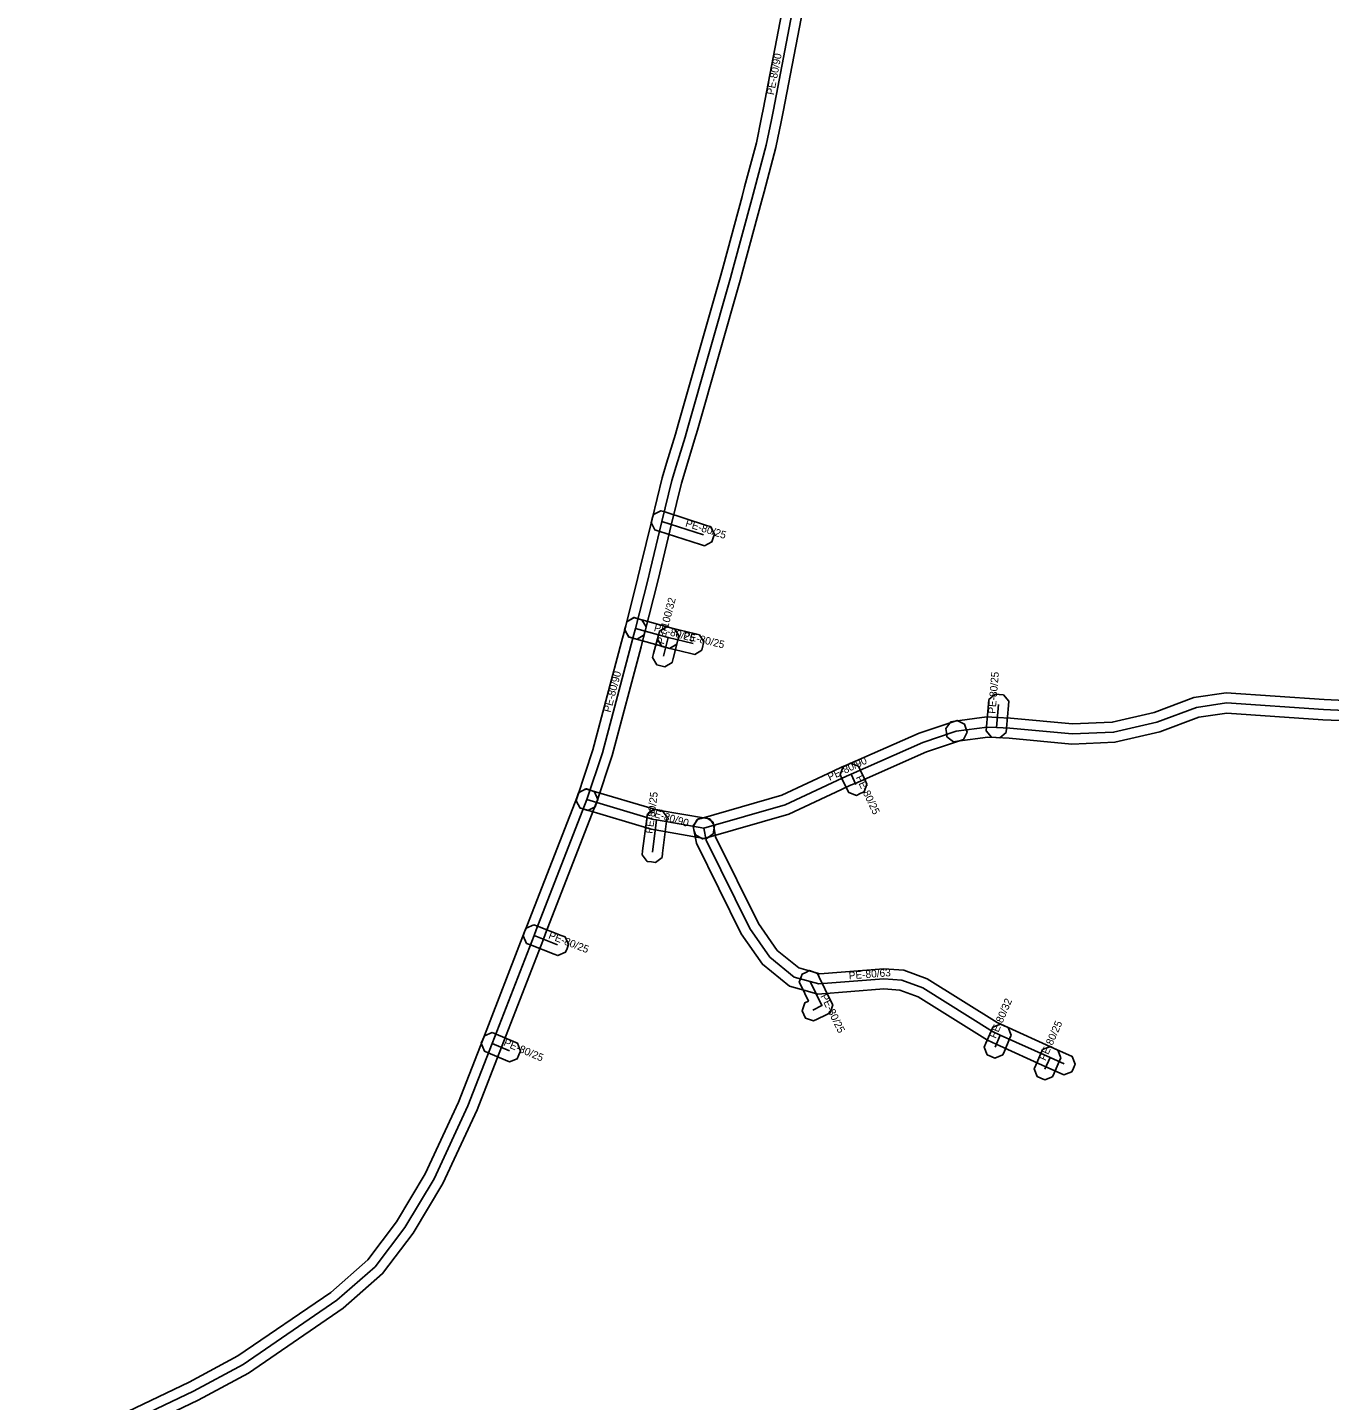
# Model space of a CAD drawing. Extents: x -569373 to -565022, y -1135090 to -1131496.
# Drawn here: x -565661.8 to -565532.3, y -1134134.8 to -1133998.2 of the extents above; entities that cross this region are included whole.
import ezdxf

# ---------------------------------------------------------------- set-up
doc = ezdxf.new("R2010")
doc.units = 0
for name, color, linetype in [('1', 7, 'Continuous'), ('24', 7, 'Continuous'), ('30', 7, 'Continuous')]:
    doc.layers.add(name, color=color, linetype=linetype)

msp = doc.modelspace()

# ---------------------------------------------------------------- linework, layer by layer
at = {"layer": '1'}
for points in [[(-565584.467, -1133995.37), (-565586.619, -1134006.586), (-565586.825, -1134007.573), (-565587.357, -1134010.131), (-565588.534, -1134014.548), (-565588.794, -1134015.52), (-565590.644, -1134022.38), (-565590.906, -1134023.357), (-565595.164, -1134038.244), (-565595.441, -1134039.212), (-565596.318, -1134042.112), (-565596.745, -1134043.523), (-565597.728, -1134047.576), (-565598.903, -1134052.424), (-565599.139, -1134053.401), (-565600.361, -1134058.216), (-565600.463, -1134058.617), (-565601.175, -1134059.041), (-565601.576, -1134058.939), (-565601.977, -1134058.837), (-565602.401, -1134058.125), (-565602.299, -1134057.724), (-565601.081, -1134052.919), (-565600.847, -1134051.954), (-565599.672, -1134047.104), (-565598.675, -1134042.997), (-565598.232, -1134041.532), (-565597.359, -1134038.648), (-565597.086, -1134037.694), (-565592.834, -1134022.823), (-565592.576, -1134021.86), (-565590.726, -1134015), (-565590.466, -1134014.032), (-565589.303, -1134009.669), (-565588.783, -1134007.165), (-565588.581, -1134006.194), (-565586.453, -1133995.11)], [(-565527.938, -1134067.272), (-565532.937, -1134067.048), (-565542.49, -1134066.385), (-565545.28, -1134066.804), (-565549.161, -1134068.239), (-565553.623, -1134069.285), (-565557.906, -1134069.472), (-565564.16, -1134068.878), (-565565.454, -1134068.819), (-565566.284, -1134068.783), (-565569.275, -1134069.191), (-565569.685, -1134069.247), (-565570.345, -1134068.745), (-565570.401, -1134068.335), (-565570.457, -1134067.925), (-565569.955, -1134067.265), (-565569.545, -1134067.209), (-565566.376, -1134066.777), (-565565.366, -1134066.821), (-565564.02, -1134066.882), (-565557.854, -1134067.468), (-565553.897, -1134067.295), (-565549.739, -1134066.321), (-565545.78, -1134064.856), (-565542.57, -1134064.375), (-565532.823, -1134065.052), (-565527.962, -1134065.268)], [(-565661.815, -1134140.62), (-565645.743, -1134132.948), (-565640.881, -1134130.325), (-565631.644, -1134124.008), (-565627.957, -1134120.776), (-565625.11, -1134117), (-565622.244, -1134112.23), (-565618.92, -1134105.078), (-565616.512, -1134098.888), (-565612.352, -1134088.156), (-565612.131, -1134087.596), (-565607.092, -1134074.638), (-565606.942, -1134074.252), (-565606.184, -1134073.918), (-565605.798, -1134074.068), (-565605.412, -1134074.218), (-565605.078, -1134074.976), (-565605.228, -1134075.362), (-565610.269, -1134088.324), (-565610.488, -1134088.884), (-565614.648, -1134099.612), (-565617.08, -1134105.862), (-565620.476, -1134113.17), (-565623.45, -1134118.12), (-565626.483, -1134122.144), (-565630.416, -1134125.592), (-565639.839, -1134132.035), (-565644.837, -1134134.732), (-565660.985, -1134142.44)]]:
    msp.add_lwpolyline(points, dxfattribs=at)
for points in [[(-565594.461, -1134049.748), (-565594.855, -1134049.622), (-565599.005, -1134048.292), (-565599.399, -1134048.166), (-565599.778, -1134047.429), (-565599.652, -1134047.035), (-565599.526, -1134046.641), (-565598.789, -1134046.262), (-565598.395, -1134046.388), (-565594.245, -1134047.718), (-565593.851, -1134047.844), (-565593.472, -1134048.581), (-565593.598, -1134048.975), (-565593.724, -1134049.369)], [(-565600.258, -1134057.819), (-565600.362, -1134058.22), (-565600.522, -1134058.84), (-565600.773, -1134059.814), (-565603.651, -1134070.617), (-565605.211, -1134075.315), (-565605.341, -1134075.708), (-565606.082, -1134076.079), (-565606.475, -1134075.949), (-565606.868, -1134075.819), (-565607.239, -1134075.078), (-565607.109, -1134074.685), (-565605.569, -1134070.043), (-565602.707, -1134059.306), (-565602.458, -1134058.34), (-565602.298, -1134057.72), (-565602.194, -1134057.319), (-565601.481, -1134056.898), (-565601.08, -1134057.002), (-565600.679, -1134057.106)], [(-565597.94, -1134059.954), (-565598.339, -1134059.843), (-565601.599, -1134058.933), (-565601.998, -1134058.822), (-565602.404, -1134058.1), (-565602.293, -1134057.701), (-565602.182, -1134057.302), (-565601.46, -1134056.896), (-565601.061, -1134057.007), (-565597.801, -1134057.917), (-565597.402, -1134058.028), (-565596.996, -1134058.75), (-565597.107, -1134059.149), (-565597.218, -1134059.548)], [(-565599.622, -1134060.869), (-565599.518, -1134060.468), (-565599.038, -1134058.628), (-565598.933, -1134058.227), (-565598.219, -1134057.808), (-565597.818, -1134057.912), (-565597.417, -1134058.017), (-565596.998, -1134058.731), (-565597.102, -1134059.132), (-565597.582, -1134060.972), (-565597.687, -1134061.373), (-565598.401, -1134061.792), (-565598.802, -1134061.688), (-565599.203, -1134061.583)], [(-565595.433, -1134060.55), (-565595.836, -1134060.452), (-565598.306, -1134059.852), (-565598.709, -1134059.754), (-565599.14, -1134059.047), (-565599.042, -1134058.644), (-565598.944, -1134058.241), (-565598.237, -1134057.81), (-565597.834, -1134057.908), (-565595.364, -1134058.508), (-565594.961, -1134058.606), (-565594.53, -1134059.313), (-565594.628, -1134059.716), (-565594.726, -1134060.119)], [(-565566.441, -1134068.15), (-565566.407, -1134067.737), (-565566.217, -1134065.457), (-565566.183, -1134065.044), (-565565.55, -1134064.509), (-565565.137, -1134064.543), (-565564.724, -1134064.577), (-565564.189, -1134065.21), (-565564.223, -1134065.623), (-565564.413, -1134067.903), (-565564.447, -1134068.316), (-565565.08, -1134068.851), (-565565.493, -1134068.817), (-565565.906, -1134068.783)], [(-565595.193, -1134076.983), (-565594.795, -1134076.869), (-565586.772, -1134074.571), (-565581.674, -1134072.177), (-565580.758, -1134071.747), (-565580.277, -1134071.542), (-565573.101, -1134068.387), (-565569.729, -1134067.252), (-565569.336, -1134067.12), (-565568.594, -1134067.488), (-565568.462, -1134067.881), (-565568.33, -1134068.274), (-565568.698, -1134069.016), (-565569.091, -1134069.148), (-565572.379, -1134070.253), (-565579.483, -1134073.378), (-565579.942, -1134073.573), (-565580.824, -1134073.987), (-565586.068, -1134076.449), (-565594.245, -1134078.791), (-565594.643, -1134078.905), (-565595.367, -1134078.503), (-565595.481, -1134078.105), (-565595.595, -1134077.707)], [(-565579.152, -1134071.659), (-565578.975, -1134072.034), (-565578.485, -1134073.074), (-565578.309, -1134073.448), (-565578.589, -1134074.228), (-565578.964, -1134074.405), (-565579.338, -1134074.581), (-565580.118, -1134074.301), (-565580.295, -1134073.926), (-565580.785, -1134072.886), (-565580.961, -1134072.512), (-565580.681, -1134071.732), (-565580.306, -1134071.555), (-565579.932, -1134071.379)], [(-565606.272, -1134073.924), (-565605.875, -1134074.042), (-565599.319, -1134075.992), (-565599.058, -1134076.033), (-565594.35, -1134076.845), (-565593.942, -1134076.915), (-565593.465, -1134077.592), (-565593.535, -1134078), (-565593.605, -1134078.408), (-565594.282, -1134078.885), (-565594.69, -1134078.815), (-565599.382, -1134078.007), (-565599.761, -1134077.948), (-565606.445, -1134075.958), (-565606.842, -1134075.84), (-565607.236, -1134075.112), (-565607.118, -1134074.715), (-565607, -1134074.318)], [(-565598.176, -1134076.733), (-565598.228, -1134077.144), (-565598.628, -1134080.334), (-565598.679, -1134080.745), (-565599.333, -1134081.254), (-565599.744, -1134081.202), (-565600.155, -1134081.151), (-565600.664, -1134080.497), (-565600.612, -1134080.086), (-565600.212, -1134076.896), (-565600.161, -1134076.485), (-565599.507, -1134075.976), (-565599.096, -1134076.028), (-565598.685, -1134076.079)], [(-565593.607, -1134077.248), (-565593.535, -1134077.656), (-565593.35, -1134078.705), (-565589.077, -1134087.32), (-565587.219, -1134089.994), (-565585.071, -1134091.742), (-565583.681, -1134092.127), (-565583, -1134092.319), (-565576.633, -1134091.827), (-565574.618, -1134091.973), (-565572.309, -1134092.817), (-565565.346, -1134097.167), (-565564.617, -1134097.499), (-565559.667, -1134099.739), (-565558.257, -1134100.379), (-565557.88, -1134100.55), (-565557.588, -1134101.326), (-565557.759, -1134101.703), (-565557.93, -1134102.08), (-565558.706, -1134102.372), (-565559.083, -1134102.201), (-565560.493, -1134101.561), (-565565.443, -1134099.321), (-565566.294, -1134098.933), (-565573.191, -1134094.623), (-565575.042, -1134093.947), (-565576.627, -1134093.833), (-565583.2, -1134094.341), (-565584.219, -1134094.053), (-565586.009, -1134093.558), (-565588.701, -1134091.366), (-565590.803, -1134088.34), (-565595.27, -1134079.335), (-565595.505, -1134078.004), (-565595.577, -1134077.596), (-565595.102, -1134076.917), (-565594.694, -1134076.845), (-565594.286, -1134076.773)], [(-565611.445, -1134087.437), (-565611.059, -1134087.587), (-565608.709, -1134088.497), (-565608.323, -1134088.647), (-565607.987, -1134089.405), (-565608.137, -1134089.791), (-565608.287, -1134090.177), (-565609.045, -1134090.513), (-565609.431, -1134090.363), (-565611.781, -1134089.453), (-565612.167, -1134089.303), (-565612.503, -1134088.545), (-565612.353, -1134088.159), (-565612.203, -1134087.773)], [(-565583.232, -1134092.28), (-565583.051, -1134092.652), (-565581.881, -1134095.052), (-565581.7, -1134095.424), (-565581.969, -1134096.207), (-565582.341, -1134096.388), (-565583.241, -1134096.828), (-565583.613, -1134097.01), (-565584.396, -1134096.741), (-565584.578, -1134096.369), (-565584.76, -1134095.997), (-565584.491, -1134095.214), (-565584.119, -1134095.032), (-565584.117, -1134095.03), (-565584.849, -1134093.528), (-565585.03, -1134093.156), (-565584.76, -1134092.372), (-565584.388, -1134092.191), (-565584.016, -1134092.01)], [(-565563.947, -1134098.424), (-565564.111, -1134098.805), (-565564.631, -1134100.015), (-565564.795, -1134100.396), (-565565.564, -1134100.703), (-565565.945, -1134100.539), (-565566.326, -1134100.375), (-565566.633, -1134099.606), (-565566.469, -1134099.225), (-565565.949, -1134098.015), (-565565.785, -1134097.634), (-565565.016, -1134097.327), (-565564.635, -1134097.491), (-565564.254, -1134097.655)], [(-565615.568, -1134098.168), (-565615.187, -1134098.331), (-565613.457, -1134099.071), (-565613.076, -1134099.234), (-565612.768, -1134100.002), (-565612.931, -1134100.383), (-565613.094, -1134100.764), (-565613.862, -1134101.072), (-565614.243, -1134100.909), (-565615.973, -1134100.169), (-565616.354, -1134100.006), (-565616.662, -1134099.238), (-565616.499, -1134098.857), (-565616.336, -1134098.476)], [(-565558.998, -1134100.676), (-565559.166, -1134101.055), (-565559.676, -1134102.205), (-565559.844, -1134102.584), (-565560.616, -1134102.882), (-565560.995, -1134102.714), (-565561.374, -1134102.546), (-565561.672, -1134101.774), (-565561.504, -1134101.395), (-565560.994, -1134100.245), (-565560.826, -1134099.866), (-565560.054, -1134099.568), (-565559.675, -1134099.736), (-565559.296, -1134099.904)]]:
    msp.add_lwpolyline(points, close=True, dxfattribs=at)
at = {"layer": '24'}
for points in [[(-565585.46, -1133995.24), (-565587.6, -1134006.39), (-565587.804, -1134007.369), (-565588.33, -1134009.9), (-565589.5, -1134014.29), (-565589.76, -1134015.26), (-565591.61, -1134022.12), (-565591.87, -1134023.09), (-565596.125, -1134037.969), (-565596.4, -1134038.93), (-565597.275, -1134041.822), (-565597.71, -1134043.26), (-565598.7, -1134047.34), (-565599.875, -1134052.189), (-565600.11, -1134053.16), (-565601.33, -1134057.97)], [(-565594.55, -1134048.67), (-565598.7, -1134047.34)], [(-565569.41, -1134068.2), (-565566.33, -1134067.78), (-565565.41, -1134067.82), (-565564.09, -1134067.88), (-565557.88, -1134068.47), (-565553.76, -1134068.29), (-565549.45, -1134067.28), (-565545.53, -1134065.83), (-565542.53, -1134065.38), (-565532.88, -1134066.05), (-565527.95, -1134066.27), (-565527.37, -1134066.23), (-565522.24, -1134065.89), (-565521.35, -1134065.83), (-565508.81, -1134064.69), (-565504.75, -1134064.72), (-565501.7, -1134065.16), (-565497.75, -1134066.92), (-565495.54, -1134067.91), (-565492.02, -1134070.62), (-565485.93, -1134064.67), (-565478.46, -1134058.39), (-565476.6, -1134056.73)], [(-565601.33, -1134057.97), (-565601.49, -1134058.59), (-565601.74, -1134059.56), (-565604.61, -1134070.33), (-565606.16, -1134075)], [(-565598.07, -1134058.88), (-565601.33, -1134057.97)], [(-565598.55, -1134060.72), (-565598.07, -1134058.88)], [(-565595.6, -1134059.48), (-565598.07, -1134058.88)], [(-565565.41, -1134067.82), (-565565.22, -1134065.54)], [(-565594.52, -1134077.83), (-565586.42, -1134075.51), (-565581.249, -1134073.082), (-565580.35, -1134072.66), (-565579.88, -1134072.46), (-565572.74, -1134069.32), (-565569.41, -1134068.2)], [(-565579.88, -1134072.46), (-565579.39, -1134073.5)], [(-565606.16, -1134075), (-565611.2, -1134087.96), (-565611.42, -1134088.52), (-565615.58, -1134099.25), (-565618, -1134105.47), (-565621.36, -1134112.7), (-565624.28, -1134117.56), (-565627.22, -1134121.46), (-565631.03, -1134124.8), (-565640.36, -1134131.18), (-565645.29, -1134133.84), (-565661.4, -1134141.53)], [(-565606.16, -1134075), (-565599.54, -1134076.97), (-565599.22, -1134077.02), (-565594.52, -1134077.83)], [(-565599.22, -1134077.02), (-565599.62, -1134080.21)], [(-565594.52, -1134077.83), (-565594.31, -1134079.02), (-565589.94, -1134087.83), (-565587.96, -1134090.68), (-565585.54, -1134092.65), (-565583.95, -1134093.09), (-565583.1, -1134093.33), (-565576.63, -1134092.83), (-565574.83, -1134092.96), (-565572.75, -1134093.72), (-565565.82, -1134098.05), (-565565.03, -1134098.41), (-565560.08, -1134100.65), (-565558.67, -1134101.29)], [(-565611.42, -1134088.52), (-565609.07, -1134089.43)], [(-565583.95, -1134093.09), (-565582.78, -1134095.49), (-565583.68, -1134095.93)], [(-565565.03, -1134098.41), (-565565.55, -1134099.62)], [(-565615.58, -1134099.25), (-565613.85, -1134099.99)], [(-565560.08, -1134100.65), (-565560.59, -1134101.8)]]:
    msp.add_lwpolyline(points, dxfattribs=at)

# ---------------------------------------------------------------- texts
at = {"layer": '30'}
for s, rotation, p in [('PE-80/90', 79.13544, (-565587.563, -1134004.955)), ('PE-80/25', 342.23028, (-565596.425, -1134047.805)), ('PE-100/32', 75.37913, (-565598.51, -1134059.6)), ('PE-80/25', 344.4034, (-565599.548, -1134058.212)), ('PE-80/25', 346.34645, (-565596.635, -1134058.98)), ('PE-80/90', 75.07852, (-565603.81, -1134066.377)), ('PE-80/25', 85.23636, (-565565.515, -1134066.48)), ('PE-80/90', 25.15201, (-565582.002, -1134073.142)), ('PE-80/25', 295.22765, (-565579.435, -1134072.78)), ('PE-80/25', 82.85288, (-565599.62, -1134078.415)), ('PE-80/90', 343.42789, (-565600.161, -1134076.526)), ('PE-80/25', 338.8319, (-565610.045, -1134088.775)), ('PE-80/63', 4.41902, (-565580.078, -1134092.881)), ('PE-80/25', 295.98923, (-565582.946, -1134094.54)), ('PE-80/32', 66.74429, (-565565.49, -1134098.815)), ('PE-80/25', 66.08375, (-565560.535, -1134101.025)), ('PE-80/25', 336.84139, (-565614.515, -1134099.42))]:
    msp.add_text(s, height=0.75, rotation=rotation, dxfattribs=at).set_placement(p)

doc.saveas('drawing.dxf')
